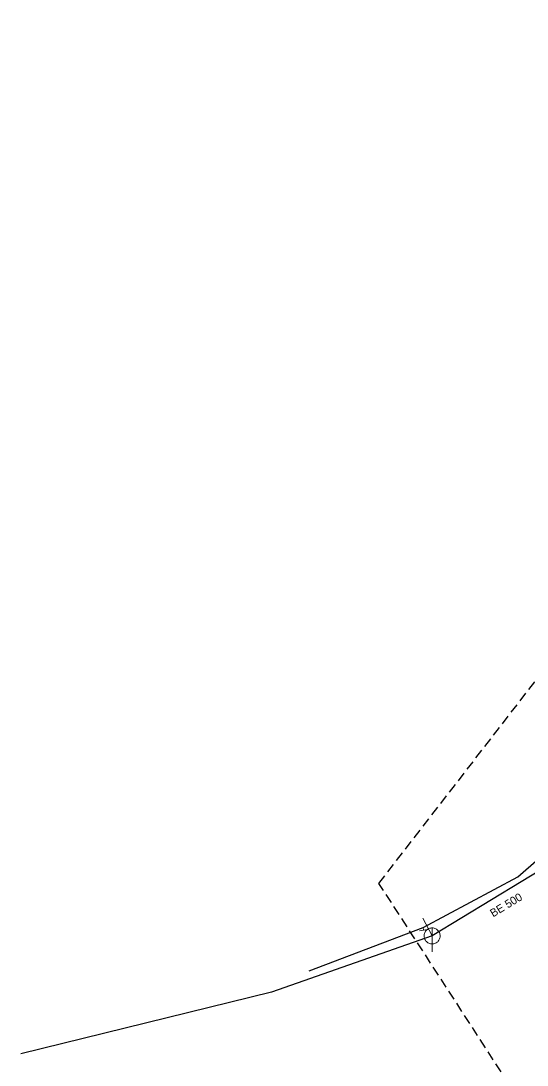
# Model space of a CAD drawing. Extents: x -687013 to -686506, y -973869 to -973672.
# Drawn here: x -687012.7 to -686949.6, y -973802 to -973671.6 of the extents above; entities that cross this region are included whole.
import ezdxf

# ---------------------------------------------------------------- set-up
doc = ezdxf.new("R2010")
doc.units = 0
doc.header["$LTSCALE"] = 0.4
doc.linetypes.add('MEDIUM_DASHED', pattern=[4.5, 3, -1.5])
doc.layers.add('1', color=7, linetype='Continuous')
for name, color, linetype, lineweight in [('11', 7, 'Continuous', 13), ('14', 7, 'Continuous', 25), ('17', 7, 'Continuous', 25), ('22', 7, 'Continuous', 13), ('34', 7, 'Continuous', 13), ('63', 7, 'MEDIUM_DASHED', 25)]:
    doc.layers.add(name, color=color, linetype=linetype, lineweight=lineweight)

msp = doc.modelspace()

# ---------------------------------------------------------------- linework, layer by layer
at = {"layer": '11'}
msp.add_line((-686962.591, -973783.689), (-686961.432, -973785.892), dxfattribs=at)
at = {"layer": '14'}
msp.add_line((-686943.166, -973774.771), (-686961.432, -973785.892), dxfattribs=at)
at = {"layer": '14', "lineweight": 13}
msp.add_line((-686962.561, -973784.848), (-686962.51, -973785.159), dxfattribs=at)
at = {"layer": '14'}
msp.add_lwpolyline([(-686961.432, -973785.892), (-686981.489, -973792.906), (-687012.736, -973800.616)], dxfattribs=at)
at = {"layer": '17'}
msp.add_lwpolyline([(-686976.761, -973790.276), (-686962.561, -973784.848), (-686950.728, -973778.526), (-686943.195, -973771.934), (-686939.23, -973761.912), (-686935.397, -973746.442), (-686925.984, -973737.294), (-686915.07, -973732.61), (-686899.151, -973729.811), (-686884.189, -973728.62)], dxfattribs=at)
at = {"layer": '22'}
msp.add_line((-686961.432, -973787.892), (-686961.431, -973784.892), dxfattribs=at)
msp.add_lwpolyline([(-686960.432, -973785.892), (-686960.437, -973785.783), (-686960.455, -973785.675), (-686960.485, -973785.569), (-686960.525, -973785.468), (-686960.577, -973785.371), (-686960.639, -973785.281), (-686960.711, -973785.198), (-686960.791, -973785.124), (-686960.879, -973785.058), (-686960.973, -973785.003), (-686961.073, -973784.958), (-686961.178, -973784.925), (-686961.285, -973784.903), (-686961.394, -973784.893), (-686961.504, -973784.895), (-686961.612, -973784.909), (-686961.719, -973784.934), (-686961.822, -973784.971), (-686961.92, -973785.02), (-686962.012, -973785.078), (-686962.098, -973785.147), (-686962.175, -973785.224), (-686962.244, -973785.31), (-686962.303, -973785.402), (-686962.351, -973785.5), (-686962.388, -973785.603), (-686962.414, -973785.71), (-686962.428, -973785.818), (-686962.431, -973785.928), (-686962.421, -973786.037), (-686962.4, -973786.144), (-686962.366, -973786.248), (-686962.322, -973786.348), (-686962.267, -973786.443), (-686962.201, -973786.531), (-686962.127, -973786.611), (-686962.044, -973786.683), (-686961.954, -973786.745), (-686961.858, -973786.797), (-686961.756, -973786.838), (-686961.651, -973786.868), (-686961.543, -973786.886), (-686961.433, -973786.892), (-686961.324, -973786.886), (-686961.216, -973786.868), (-686961.111, -973786.839), (-686961.009, -973786.798), (-686960.912, -973786.746), (-686960.822, -973786.684), (-686960.739, -973786.613), (-686960.664, -973786.533), (-686960.599, -973786.445), (-686960.543, -973786.351), (-686960.499, -973786.251), (-686960.465, -973786.147), (-686960.443, -973786.039), (-686960.433, -973785.93)], close=True, dxfattribs=at)
at = {"layer": '34'}
msp.add_line((-686962.016, -973785.076), (-686963.003, -973785.24), dxfattribs=at)
at = {"layer": '63'}
msp.add_lwpolyline([(-686909.784, -973869.363), (-686968.065, -973779.329), (-686968.065, -973779.329), (-686933.901, -973735.117), (-686933.901, -973735.117), (-686846.279, -973716.226), (-686846.279, -973716.226), (-686793.223, -973715.824), (-686793.223, -973715.824), (-686767.901, -973696.129), (-686767.901, -973696.129), (-686632.047, -973671.611), (-686632.047, -973671.611), (-686619.587, -973774.908), (-686619.587, -973774.908), (-686749.412, -973818.317), (-686749.412, -973818.317)], close=True, dxfattribs=at)

# ---------------------------------------------------------------- texts
at = {"layer": '1'}
msp.add_text('BE 500', height=1, rotation=31, dxfattribs=at).set_placement((-686953.828, -973783.587))

doc.saveas('drawing.dxf')
